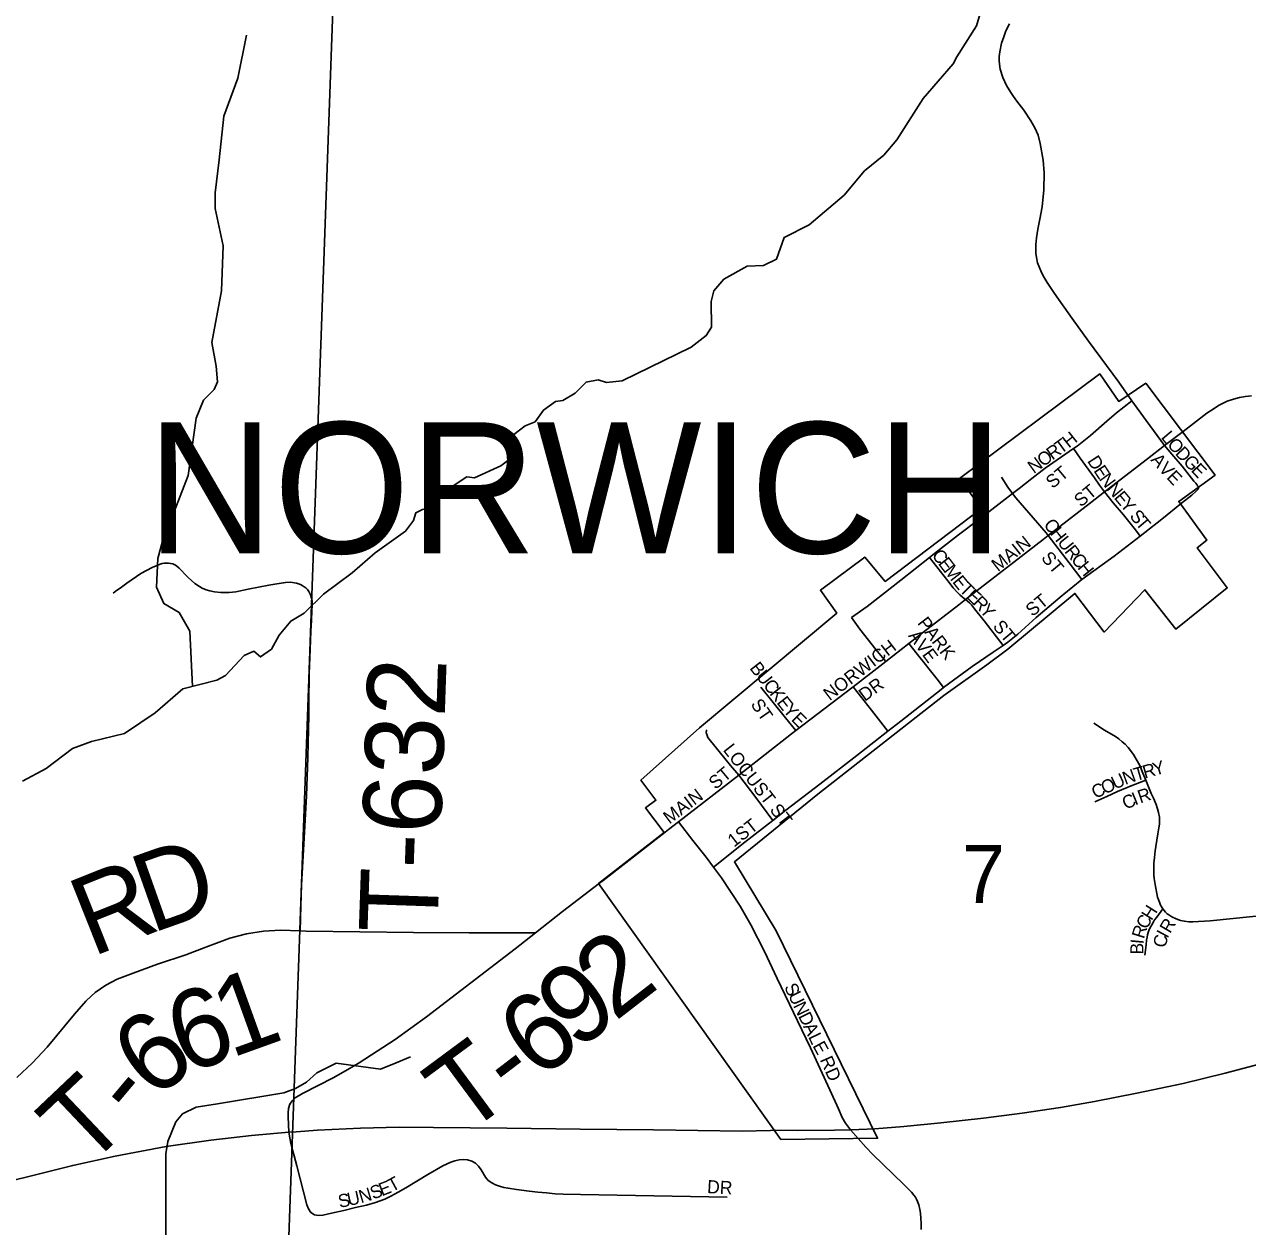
# Model space of a CAD drawing. Extents: x 0 to 34, y 0 to 22.
# Drawn here: x 24.426 to 25.311, y 16.381 to 17.25 of the extents above; entities that cross this region are included whole.
import ezdxf

# ---------------------------------------------------------------- set-up
doc = ezdxf.new("R2010")
doc.units = 0
for name, color, linetype in [('GM_X_City_Street', 7, 'Continuous'), ('GM_X_City_Street_Text', 7, 'Continuous'), ('GM_X_Corporation', 7, 'Continuous'), ('GM_X_Corporation_Text', 7, 'Continuous'), ('GM_X_County_Road', 7, 'Continuous'), ('GM_X_Minor_River', 7, 'Continuous'), ('GM_X_Section', 7, 'Continuous'), ('GM_X_Section_Text', 7, 'Continuous'), ('GM_X_Township_Road', 7, 'Continuous'), ('GM_X_Township_Road_Text', 7, 'Continuous'), ('GM_X_Township_Subdivision', 7, 'Continuous'), ('GM_X_Township_Subdivision_Text', 7, 'Continuous'), ('GM_X_US_Route', 7, 'Continuous')]:
    doc.layers.add(name, color=color, linetype=linetype)

msp = doc.modelspace()

# ---------------------------------------------------------------- linework, layer by layer
at = {"layer": 'GM_X_City_Street'}
for points in [[(25.18501, 16.94324), (25.18748, 16.94501), (25.19727, 16.95267), (25.20895, 16.96297), (25.21602, 16.96899), (25.22715, 16.97789)], [(25.25066, 16.94541), (25.23736, 16.96356), (25.22715, 16.97789)], [(25.25066, 16.94541), (25.26414, 16.95568)], [(25.20724, 16.91192), (25.20922, 16.91347), (25.23849, 16.9359), (25.25066, 16.94541)], [(25.27534, 16.91501), (25.27527, 16.91533), (25.27518, 16.91552), (25.27507, 16.91577), (25.2749, 16.91607), (25.27465, 16.91643), (25.27404, 16.9172), (25.27328, 16.91822), (25.27202, 16.91976), (25.26342, 16.9305), (25.25593, 16.93918), (25.25066, 16.94541)], [(25.14091, 16.9108), (25.14554, 16.91433), (25.15469, 16.92156), (25.16453, 16.929), (25.18501, 16.94324)], [(25.20724, 16.91192), (25.20378, 16.9168), (25.20001, 16.92211), (25.18983, 16.93644), (25.18501, 16.94324)], [(25.14091, 16.9108), (25.13738, 16.91549), (25.13286, 16.92264)], [(25.08076, 16.86458), (25.0845, 16.86754), (25.1018, 16.8808), (25.11657, 16.89204), (25.1238, 16.89757), (25.13344, 16.90502), (25.14091, 16.9108)], [(25.16659, 16.8804), (25.16512, 16.88226), (25.14331, 16.9076), (25.14091, 16.9108)], [(25.16659, 16.8804), (25.1972, 16.90403), (25.20724, 16.91192)], [(25.23312, 16.88005), (25.22968, 16.88441), (25.225, 16.8905), (25.22099, 16.89549), (25.21366, 16.90414), (25.20724, 16.91192)], [(25.26302, 16.90373), (25.27044, 16.9097), (25.27373, 16.9126), (25.27446, 16.91327), (25.27484, 16.9137), (25.275, 16.91391), (25.27516, 16.91416), (25.27523, 16.91433), (25.27529, 16.91448), (25.27532, 16.91463), (25.27533, 16.9147), (25.27534, 16.91501)], [(25.23312, 16.88005), (25.23651, 16.88271), (25.24871, 16.8923), (25.26302, 16.90373)], [(25.10694, 16.83421), (25.16301, 16.87764), (25.16659, 16.8804)], [(25.19088, 16.84873), (25.18178, 16.86069), (25.16659, 16.8804)], [(25.19088, 16.84873), (25.21444, 16.86541), (25.23312, 16.88005)], [(25.02446, 16.82126), (25.03569, 16.82905), (25.06008, 16.84823), (25.08076, 16.86458)], [(25.10694, 16.83421), (25.10466, 16.8359), (25.10276, 16.83756), (25.10077, 16.83953), (25.09793, 16.84272), (25.09404, 16.84758), (25.08076, 16.86458)], [(25.17675, 16.83708), (25.17785, 16.83802), (25.19088, 16.84873)], [(25.06591, 16.80232), (25.07574, 16.81002), (25.10196, 16.83033), (25.10694, 16.83421)], [(25.13413, 16.80099), (25.12038, 16.81877), (25.11335, 16.82739), (25.11106, 16.83025), (25.10971, 16.83168), (25.10694, 16.83421)], [(25.13413, 16.80099), (25.13743, 16.80339), (25.14457, 16.80907), (25.15798, 16.82125), (25.17675, 16.83708)], [(25.04917, 16.78929), (25.04198, 16.79808), (25.03046, 16.81271), (25.02446, 16.82126)], [(25.04917, 16.78929), (25.06591, 16.80232)], [(25.09102, 16.77055), (25.08626, 16.77652), (25.07207, 16.79451), (25.06591, 16.80232)], [(25.09102, 16.77055), (25.11154, 16.7858), (25.12686, 16.79615), (25.13413, 16.80099)], [(25.02555, 16.77104), (25.03834, 16.78095), (25.04917, 16.78929)], [(24.98407, 16.73941), (24.97667, 16.74853), (24.95874, 16.77071)], [(24.98407, 16.73941), (25.02555, 16.77104)], [(25.05073, 16.73901), (25.03895, 16.75422), (25.02555, 16.77104)], [(25.05073, 16.73901), (25.06004, 16.74625), (25.0892, 16.7692), (25.09102, 16.77055)], [(24.94287, 16.70727), (24.93696, 16.71425), (24.92161, 16.73315), (24.92061, 16.73449), (24.91996, 16.73584), (24.9197, 16.73655), (24.9195, 16.7373), (24.91944, 16.7379), (24.91943, 16.73856), (24.91951, 16.73911), (24.91964, 16.73961), (24.91982, 16.74006)], [(24.94287, 16.70727), (24.98111, 16.73697), (24.98407, 16.73941)], [(24.96749, 16.67452), (24.97691, 16.68189), (25.00153, 16.7006), (25.02836, 16.72147), (25.05073, 16.73901)], [(24.89927, 16.67347), (24.94287, 16.70727)], [(24.96749, 16.67452), (24.95525, 16.69094), (24.94287, 16.70727)], [(24.89218, 16.66794), (24.89927, 16.67347)], [(24.92467, 16.64074), (24.91926, 16.64799), (24.90963, 16.65999), (24.89927, 16.67347)], [(24.94724, 16.65865), (24.96749, 16.67452)], [(24.92467, 16.64074), (24.94724, 16.65865)], [(25.02368, 16.45092), (25.02007, 16.45559), (25.01759, 16.45981), (25.01501, 16.46596), (25.00867, 16.47976), (24.99487, 16.51011), (24.98546, 16.5296), (24.97055, 16.56012), (24.96146, 16.57972), (24.95174, 16.59901), (24.94398, 16.61239), (24.93038, 16.63309), (24.92467, 16.64074)]]:
    msp.add_lwpolyline(points, dxfattribs=at)
at = {"layer": 'GM_X_Corporation'}
msp.add_lwpolyline([(24.8415, 16.62881), (24.88897, 16.66581), (24.87538, 16.68348), (24.88303, 16.68906), (24.87215, 16.70361), (24.91457, 16.74137), (25.01372, 16.82433), (25.00191, 16.8409), (25.03395, 16.8648), (25.04879, 16.84726), (25.11847, 16.89987), (25.10254, 16.92156), (25.2039, 16.99725), (25.21762, 16.97733), (25.23719, 16.99049), (25.28734, 16.92409), (25.26099, 16.90512), (25.2814, 16.87718), (25.27438, 16.87161), (25.29613, 16.84256), (25.25901, 16.81269), (25.23658, 16.8412), (25.20722, 16.81056), (25.18595, 16.83854), (25.13745, 16.79825), (25.12215, 16.78706), (25.09118, 16.76467), (25.00015, 16.69341), (24.9397, 16.64453), (24.96993, 16.59454), (25.04322, 16.44474), (24.97336, 16.44385)], close=True, dxfattribs=at)
at = {"layer": 'GM_X_County_Road'}
for points in [[(25.22715, 16.97789), (25.21774, 16.99116), (25.19589, 17.021), (25.18387, 17.03731), (25.17112, 17.05541), (25.16593, 17.06342), (25.16311, 17.06802), (25.16133, 17.07172), (25.15999, 17.07469), (25.15896, 17.07751), (25.15807, 17.08137), (25.15777, 17.08448), (25.15762, 17.08774), (25.15762, 17.09071), (25.15821, 17.0956), (25.15911, 17.10184), (25.16065, 17.10903), (25.16229, 17.1181), (25.16342, 17.13033), (25.1636, 17.14267), (25.16293, 17.15181), (25.16094, 17.16388), (25.15936, 17.16976), (25.157, 17.17513), (25.15405, 17.18027), (25.14893, 17.1879), (25.14397, 17.1945), (25.14152, 17.19777), (25.13971, 17.20064), (25.13651, 17.20572), (25.13383, 17.21143), (25.13201, 17.21752), (25.13137, 17.22109), (25.13124, 17.22382), (25.13122, 17.22673), (25.13155, 17.23014), (25.13283, 17.23631), (25.13451, 17.24093), (25.13607, 17.24516), (25.13869, 17.25028)], [(25.07481, 16.37877), (25.07474, 16.38306), (25.07454, 16.38699), (25.07432, 16.39055), (25.07391, 16.39325), (25.07311, 16.39661), (25.07221, 16.39897), (25.07143, 16.4006), (25.07057, 16.40202), (25.0695, 16.4036), (25.06776, 16.40567), (25.0655, 16.4081), (25.06203, 16.41162), (25.03975, 16.43297), (25.03486, 16.43837), (25.02368, 16.45092)]]:
    msp.add_lwpolyline(points, dxfattribs=at)
at = {"layer": 'GM_X_Minor_River'}
for points in [[(24.42503, 16.70276), (24.44202, 16.71198), (24.46123, 16.72651), (24.47483, 16.73154), (24.49866, 16.73738), (24.5209, 16.75232), (24.54086, 16.76951), (24.56544, 16.77574), (24.57186, 16.7792), (24.58539, 16.7937), (24.59219, 16.79678), (24.59714, 16.79264), (24.60506, 16.79838), (24.61067, 16.80827), (24.61894, 16.81857), (24.62874, 16.82432), (24.64266, 16.83807), (24.6634, 16.85337), (24.67996, 16.86789), (24.70183, 16.88358), (24.70783, 16.89121), (24.70931, 16.89691), (24.71422, 16.89922), (24.71914, 16.90039), (24.73343, 16.91451), (24.74626, 16.92294), (24.75194, 16.92222), (24.77082, 16.93068), (24.77685, 16.93527), (24.78097, 16.9425), (24.78014, 16.9535), (24.78843, 16.95962), (24.79561, 16.9627), (24.80161, 16.97108), (24.81028, 16.97721), (24.81558, 16.978), (24.82463, 16.98337), (24.83253, 16.99139), (24.84123, 16.99296), (24.84731, 16.9911), (24.85866, 16.99231), (24.9085, 17.01653), (24.91942, 17.02494), (24.92317, 17.03103), (24.92305, 17.04962), (24.92489, 17.05722), (24.93203, 17.06561), (24.94901, 17.07519), (24.96075, 17.07565), (24.97019, 17.08026), (24.97577, 17.09585), (24.99388, 17.10507), (25.01912, 17.12647), (25.03377, 17.14401), (25.04771, 17.15548), (25.05711, 17.16654), (25.07622, 17.19624), (25.09803, 17.22141), (25.10065, 17.22636), (25.11489, 17.24883), (25.11859, 17.26175)], [(24.54782, 16.77128), (24.54589, 16.81127), (24.53822, 16.82488), (24.5272, 16.83125), (24.52182, 16.84298), (24.52281, 16.86385), (24.52688, 16.87904), (24.53322, 16.89388), (24.54476, 16.92392), (24.55054, 16.9653), (24.55576, 16.97823), (24.56366, 16.98587), (24.5659, 16.99158), (24.56506, 17.00295), (24.56192, 17.02), (24.56887, 17.05722), (24.57017, 17.08984), (24.56431, 17.11674), (24.56423, 17.12812), (24.5671, 17.15203), (24.57068, 17.18354), (24.58072, 17.21091), (24.58696, 17.24206)], [(24.50706, 16.26247), (24.52242, 16.29676), (24.5245, 16.3256), (24.52851, 16.34839), (24.52865, 16.38443), (24.52871, 16.43336), (24.53016, 16.44247), (24.53575, 16.45654), (24.54063, 16.46226), (24.55045, 16.46726), (24.56596, 16.46963), (24.61401, 16.47753), (24.62232, 16.48062), (24.63024, 16.48522), (24.63777, 16.4921), (24.65174, 16.49901), (24.68396, 16.49467), (24.69529, 16.49929), (24.70549, 16.50353)]]:
    msp.add_lwpolyline(points, dxfattribs=at)
at = {"layer": 'GM_X_Section'}
msp.add_lwpolyline([(24.01667, 16.32239), (24.61475, 16.29304), (24.6507, 17.29407), (24.01667, 17.32351)], dxfattribs=at)
msp.add_lwpolyline([(24.6507, 17.29407), (25.63163, 17.25763), (25.60101, 16.25398), (24.61475, 16.29304)], close=True, dxfattribs=at)
at = {"layer": 'GM_X_Township_Road'}
for points in [[(25.26414, 16.95568), (25.2642, 16.95572), (25.27164, 16.9614), (25.28144, 16.96884), (25.28655, 16.97226), (25.28984, 16.97434), (25.29613, 16.97754), (25.30072, 16.97907), (25.30485, 16.9801), (25.30922, 16.981), (25.31373, 16.98145)], [(24.62569, 16.59467), (24.62628, 16.61271), (24.62685, 16.62802), (24.6287, 16.66155), (24.63026, 16.69219), (24.63135, 16.71987), (24.63193, 16.75066), (24.63205, 16.75966), (24.63235, 16.78038), (24.6324, 16.78643), (24.63291, 16.79816), (24.63348, 16.81117), (24.63386, 16.81902), (24.63428, 16.82618), (24.63453, 16.82992), (24.63449, 16.83158), (24.63437, 16.8329), (24.63396, 16.83505), (24.63318, 16.83761), (24.63204, 16.83995), (24.63095, 16.84135), (24.62977, 16.84254), (24.62866, 16.84336), (24.62733, 16.84426), (24.62601, 16.84494), (24.62459, 16.84553), (24.62313, 16.84601), (24.62163, 16.84632), (24.62013, 16.84652), (24.61856, 16.84659), (24.61513, 16.84637), (24.61367, 16.84628), (24.60888, 16.84544), (24.60323, 16.84449), (24.58814, 16.84153), (24.57918, 16.83978), (24.57673, 16.83944), (24.57443, 16.83925), (24.57086, 16.83912), (24.5685, 16.83925), (24.56375, 16.83973), (24.56047, 16.84035), (24.55772, 16.84108), (24.55488, 16.84229), (24.55287, 16.84353), (24.54972, 16.84567), (24.54476, 16.85016), (24.54292, 16.85203), (24.53983, 16.85543), (24.5383, 16.85694), (24.53647, 16.85846), (24.53503, 16.85933), (24.53358, 16.85989), (24.53208, 16.86029), (24.53054, 16.86051), (24.52888, 16.86052), (24.52746, 16.86047), (24.52609, 16.8602), (24.52445, 16.85981), (24.51873, 16.85738), (24.51058, 16.85292), (24.50051, 16.84608), (24.49555, 16.84246), (24.49304, 16.84066), (24.49052, 16.83885)], [(24.84491, 16.63111), (24.88979, 16.66608), (24.89218, 16.66794)], [(24.79591, 16.59324), (24.81544, 16.60854), (24.84232, 16.62909), (24.84491, 16.63111)], [(24.42084, 16.48869), (24.43223, 16.49917), (24.4428, 16.51048), (24.4626, 16.53435), (24.47071, 16.54374), (24.47454, 16.54745), (24.47762, 16.54997), (24.48522, 16.55533), (24.49344, 16.55967), (24.505, 16.56416), (24.52253, 16.57046), (24.54306, 16.57736), (24.5575, 16.58282), (24.57494, 16.58926), (24.58691, 16.59254), (24.59916, 16.59451), (24.61154, 16.59515), (24.62569, 16.59467)], [(24.62569, 16.59467), (24.63015, 16.59451), (24.70763, 16.59341), (24.74794, 16.59328), (24.79591, 16.59324)], [(24.66033, 16.49453), (24.66848, 16.49929), (24.69453, 16.51616), (24.71721, 16.53247), (24.78121, 16.58171), (24.79591, 16.59324)], [(24.61753, 16.449), (24.61716, 16.4601), (24.61705, 16.46321), (24.61738, 16.4663), (24.61832, 16.46926), (24.61994, 16.47189), (24.62216, 16.474), (24.62755, 16.47712), (24.64973, 16.48835), (24.66033, 16.49453)]]:
    msp.add_lwpolyline(points, dxfattribs=at)
at = {"layer": 'GM_X_Township_Subdivision'}
for points in [[(25.23713, 16.70353), (25.23505, 16.70858), (25.23279, 16.71422), (25.22825, 16.72219), (25.22454, 16.72709), (25.22229, 16.72954), (25.22017, 16.7314), (25.21762, 16.73344), (25.21525, 16.73507), (25.20732, 16.73979), (25.19956, 16.74478)], [(25.20033, 16.68779), (25.20893, 16.69188), (25.21683, 16.69544), (25.22654, 16.69959), (25.23713, 16.70353)], [(25.24951, 16.61057), (25.24794, 16.61318), (25.247, 16.61547), (25.24575, 16.61896), (25.24387, 16.62806), (25.24323, 16.6324), (25.24297, 16.63515), (25.24293, 16.64029), (25.24313, 16.64356), (25.2434, 16.64766), (25.24395, 16.65256), (25.24436, 16.65561), (25.246, 16.6647), (25.24657, 16.669), (25.24701, 16.67176), (25.24714, 16.67397), (25.24701, 16.67693), (25.2465, 16.68009), (25.24575, 16.68273), (25.2447, 16.68599), (25.24266, 16.69046), (25.2411, 16.69384), (25.23713, 16.70353)], [(25.23654, 16.57696), (25.23693, 16.58071), (25.23737, 16.58462), (25.23781, 16.58799), (25.23813, 16.59006), (25.23841, 16.59168), (25.23891, 16.59339), (25.23946, 16.59488), (25.23997, 16.59607), (25.2415, 16.59902), (25.24266, 16.60111), (25.24359, 16.6026), (25.24507, 16.60458), (25.24951, 16.61057)], [(25.3254, 16.60551), (25.31448, 16.60499), (25.28369, 16.60181), (25.27131, 16.60114), (25.26836, 16.60122), (25.26515, 16.6016), (25.26224, 16.60221), (25.25921, 16.60325), (25.256, 16.60475), (25.25377, 16.60618), (25.2527, 16.60701), (25.25145, 16.60816), (25.24951, 16.61057)], [(24.61753, 16.449), (24.61912, 16.44086), (24.62004, 16.43717), (24.62152, 16.432), (24.62345, 16.42477), (24.63065, 16.39654), (24.63184, 16.39364), (24.63358, 16.39106), (24.6361, 16.38933), (24.63914, 16.38879), (24.64217, 16.38911), (24.64832, 16.39049), (24.65736, 16.39254), (24.66586, 16.39458), (24.67374, 16.39643), (24.68021, 16.39832), (24.68696, 16.40074), (24.69121, 16.40285), (24.694, 16.40422), (24.69674, 16.40568), (24.70211, 16.40883), (24.71816, 16.41845), (24.729, 16.42469), (24.73468, 16.42733), (24.73764, 16.42837), (24.74068, 16.4291), (24.74377, 16.42939), (24.74685, 16.42911), (24.74979, 16.42818), (24.75245, 16.42661), (24.75474, 16.4245), (24.75662, 16.42201), (24.75969, 16.41658), (24.76169, 16.41421), (24.76424, 16.41243), (24.76705, 16.41107), (24.76999, 16.41002), (24.77301, 16.40917), (24.77606, 16.40852), (24.78223, 16.4076), (24.79145, 16.40649), (24.79766, 16.40582), (24.80387, 16.40523), (24.81006, 16.40463), (24.81599, 16.40428), (24.82848, 16.40401), (24.93461, 16.40219)]]:
    msp.add_lwpolyline(points, dxfattribs=at)
at = {"layer": 'GM_X_US_Route'}
for points in [[(25.03569, 16.45138), (25.04131, 16.4516), (25.06217, 16.45318), (25.08897, 16.45586), (25.11994, 16.45925), (25.14773, 16.46291), (25.17549, 16.46701), (25.20007, 16.47126), (25.23067, 16.4772), (25.26419, 16.48442), (25.2945, 16.49173), (25.32461, 16.49982)], [(24.41959, 16.41469), (24.42867, 16.41694), (24.4613, 16.42503), (24.49205, 16.43178), (24.52899, 16.43879), (24.56109, 16.44338), (24.59048, 16.44661), (24.61753, 16.449), (24.6228, 16.44946), (24.63827, 16.45055), (24.66931, 16.45195), (24.69727, 16.45262), (24.72212, 16.45248), (24.77516, 16.45199), (24.82818, 16.45129), (24.88124, 16.45079), (24.94539, 16.44994), (24.9658, 16.45039)], [(24.9658, 16.45039), (24.96965, 16.45047), (24.98562, 16.45027), (25.012, 16.45049), (25.02368, 16.45092), (25.03569, 16.45138)]]:
    msp.add_lwpolyline(points, dxfattribs=at)

# ---------------------------------------------------------------- texts
at = {"layer": 'GM_X_City_Street_Text'}
for s, rotation, p in [('H', 38.70604, (25.18151, 16.94321)), ('L', 310.29895, (25.24776, 16.95115)), ('R', 36.00165, (25.16966, 16.93458)), ('T', 36.00342, (25.17573, 16.93899)), ('O', 311.0499, (25.25215, 16.94597)), ('D', 313.27945, (25.2579, 16.93938)), ('N', 36.01291, (25.15618, 16.92479)), ('O', 36.01291, (25.16292, 16.92969)), ('D', 303.12011, (25.19455, 16.9343)), ('A', 310.94742, (25.24028, 16.93484)), ('G', 313.66151, (25.26366, 16.93327)), ('ST', 39.7984, (25.16984, 16.91385)), ('E', 303.10957, (25.1991, 16.92733)), ('V', 312.67451, (25.24595, 16.92831)), ('E', 313.16147, (25.25165, 16.92212)), ('E', 313.66688, (25.26941, 16.92724)), ('ST', 39.80915, (25.19025, 16.90054)), ('N', 306.35362, (25.20308, 16.92126)), ('N', 309.90265, (25.20842, 16.91404)), ('E', 309.93151, (25.21376, 16.90765)), ('Y', 309.96622, (25.21804, 16.90254)), ('C', 305.38803, (25.16291, 16.88843)), ('S', 309.94421, (25.225, 16.89423)), ('T', 309.97911, (25.22928, 16.88911)), ('H', 308.27373, (25.16757, 16.8819)), ('MAIN', 38.42188, (25.13028, 16.8539)), ('U', 308.65718, (25.17277, 16.87531)), ('R', 308.65223, (25.17798, 16.8688)), ('C', 307.80257, (25.08198, 16.86607)), ('E', 307.85428, (25.08659, 16.86013)), ('ST', 309.80916, (25.16107, 16.86405)), ('C', 308.65223, (25.18266, 16.86294)), ('M', 307.80629, (25.09068, 16.85487)), ('H', 308.65718, (25.18735, 16.85708)), ('E', 308.7916, (25.09691, 16.84683)), ('T', 314.65688, (25.1018, 16.84085)), ('E', 316.64431, (25.10674, 16.83586)), ('ST', 39.7984, (25.15525, 16.82137)), ('R', 313.71171, (25.11149, 16.83137)), ('Y', 310.43533, (25.11658, 16.82605)), ('PARK', 307.47129, (25.07166, 16.81707)), ('ST', 309.80916, (25.12609, 16.81448)), ('NORWICH', 37.57001, (25.00865, 16.76059)), ('AVE', 306.4679, (25.06507, 16.80787)), ('B', 308.20088, (24.9503, 16.78444)), ('U', 308.19897, (24.95493, 16.77854)), ('DR', 36.25889, (25.03403, 16.76011)), ('C', 308.17946, (24.96009, 16.772)), ('K', 308.21028, (24.96473, 16.7661)), ('ST', 304.69079, (24.95113, 16.75842)), ('E', 308.21529, (24.96988, 16.75955)), ('Y', 310.54023, (24.97427, 16.75398)), ('E', 314.74506, (24.9802, 16.74709)), ('LOCUST ST', 307.94025, (24.9311, 16.72531)), ('ST', 39.80915, (24.92608, 16.69637)), ('MAIN', 37.18454, (24.89281, 16.67142)), ('1ST', 37.87834, (24.93946, 16.65474)), ('S', 295.77103, (24.9755, 16.55411)), ('U', 295.77341, (24.9784, 16.5481)), ('N', 295.75372, (24.98202, 16.5406)), ('D', 295.78436, (24.98565, 16.53309)), ('A', 295.77341, (24.98927, 16.52558)), ('L', 295.74643, (24.99289, 16.51808)), ('E', 298.60305, (24.99603, 16.51162)), ('RD', 293.95911, (25.00135, 16.50156))]:
    msp.add_text(s, height=0.00947, rotation=rotation, dxfattribs=at).set_placement(p)
at = {"layer": 'GM_X_Corporation_Text'}
msp.add_text('NORWICH', height=0.094697, rotation=0.00001, dxfattribs=at).set_placement((24.51505, 16.86755))
at = {"layer": 'GM_X_Section_Text'}
msp.add_text('7', height=0.04186, rotation=0.00001, dxfattribs=at).set_placement((25.10431, 16.61475))
at = {"layer": 'GM_X_Township_Road_Text'}
for s, height, rotation, p in [('T-632', 0.056818, 88.03576, (24.72492, 16.59252)), ('D', 0.05682, 19.53743, (24.51804, 16.59262)), ('R', 0.05682, 21.68762, (24.4752, 16.57557)), ('2', 0.05682, 37.74993, (24.85328, 16.52867)), ('1', 0.05682, 19.82015, (24.57554, 16.50243)), ('9', 0.05682, 37.941, (24.82594, 16.50735)), ('6', 0.05682, 19.46175, (24.54244, 16.49073)), ('6', 0.05682, 37.56863, (24.7981, 16.48593)), ('6', 0.05682, 38.05808, (24.51936, 16.47166)), ('T', 0.05682, 36.46523, (24.74465, 16.44597)), ('-', 0.05682, 37.3558, (24.77953, 16.47176)), ('T', 0.05682, 43.44766, (24.47109, 16.42179)), ('-', 0.05682, 50.00512, (24.50674, 16.45612))]:
    msp.add_text(s, height=height, rotation=rotation, dxfattribs=at).set_placement(p)
at = {"layer": 'GM_X_Township_Subdivision_Text'}
for s, rotation, p in [('R', 15.70864, (25.23641, 16.70468)), ('Y', 15.6997, (25.24363, 16.70671)), ('U', 24.92845, (25.21499, 16.69663)), ('N', 19.92147, (25.22234, 16.70006)), ('T', 15.97167, (25.23001, 16.70284)), ('C', 24.93622, (25.20063, 16.68995)), ('O', 24.92845, (25.20744, 16.69312)), ('R', 18.52706, (25.23317, 16.68671)), ('C', 25.63137, (25.22284, 16.68201)), ('I', 22.18283, (25.22947, 16.68519)), ('H', 57.71657, (25.24132, 16.60158)), ('C', 61.61044, (25.23784, 16.59513)), ('R', 59.65266, (25.25476, 16.59228)), ('R', 72.89369, (25.23582, 16.58842)), ('C', 79.29977, (25.25169, 16.58204)), ('I', 61.67556, (25.25282, 16.58869)), ('B', 89.12569, (25.23544, 16.57747)), ('I', 84.83328, (25.23555, 16.58478)), ('E', 21.23308, (24.68474, 16.40269)), ('T', 28.44544, (24.69213, 16.40565)), ('DR', 356.82219, (24.91982, 16.40512)), ('S', 12.39247, (24.65435, 16.39425)), ('U', 12.40671, (24.66086, 16.39568)), ('N', 16.65407, (24.66974, 16.39766)), ('S', 20.82909, (24.67844, 16.40029))]:
    msp.add_text(s, height=0.00947, rotation=rotation, dxfattribs=at).set_placement(p)

doc.saveas('drawing.dxf')
